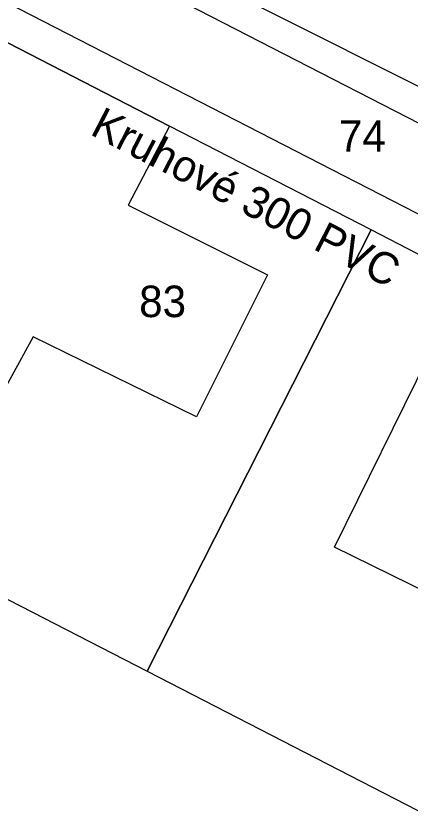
# Model space of a CAD drawing. Extents: x -559654 to -559448, y -1076607 to -1076478.
# Drawn here: x -559576.11 to -559557.35, y -1076565.25 to -1076527.73 of the extents above; entities that cross this region are included whole.
import ezdxf

# ---------------------------------------------------------------- set-up
doc = ezdxf.new("R2010")
doc.units = 0
for name, color, linetype in [('Kanalizační stoka', 7, 'Continuous'), ('Parcela-polygon', 7, 'Continuous'), ('Parcela-text', 7, 'Continuous'), ('Popis kmenové stoky', 7, 'Continuous'), ('Vodovodní řad', 7, 'Continuous')]:
    doc.layers.add(name, color=color, linetype=linetype)

msp = doc.modelspace()

# ---------------------------------------------------------------- linework, layer by layer
at = {"layer": 'Kanalizační stoka'}
msp.add_lwpolyline([(-559542.148, -1076544.787), (-559590.298, -1076520.017)], dxfattribs=at)
at = {"layer": 'Parcela-polygon'}
for p, q in [((-559587.727, -1076549.716), (-559569.856, -1076558.926)), ((-559569.856, -1076558.926), (-559551.999, -1076568.129))]:
    msp.add_line(p, q, dxfattribs=at)
for points in [[(-559598.18, -1076518.16), (-559629.27, -1076502.23), (-559633.72, -1076500.39), (-559623.33, -1076497.36), (-559616.19, -1076501.28), (-559573.81, -1076522.62), (-559555.89, -1076531.62), (-559538.18, -1076540.8), (-559520.56, -1076549.81), (-559502.55, -1076559.13), (-559485.32, -1076568.19), (-559489.07, -1076574.14), (-559505.11, -1076565.7), (-559518.69, -1076558.79), (-559538.34, -1076548.73), (-559546.54, -1076544.48), (-559559.21, -1076537.91), (-559568.79, -1076532.99), (-559577, -1076528.76), (-559595.22, -1076519.64)], [(-559568.79, -1076532.99), (-559570.76, -1076536.75), (-559564.14, -1076540.06), (-559567.52, -1076546.81), (-559575.28, -1076543.01), (-559577.42, -1076546.89), (-559581.41, -1076544.47), (-559584.1, -1076543.03), (-559584.34, -1076542.9), (-559579.53, -1076533.07), (-559577, -1076528.76)], [(-559556.49, -1076543.97), (-559548.32, -1076548.02), (-559546.54, -1076544.48), (-559538.34, -1076548.73), (-559542.4, -1076556.72), (-559545.15, -1076562.4), (-559547.78, -1076561.13), (-559550.05, -1076564.71), (-559551.63, -1076563.88), (-559549.91, -1076560.67), (-559552.84, -1076557), (-559560.94, -1076553.02)]]:
    msp.add_lwpolyline(points, close=True, dxfattribs=at)
for points in [[(-559548.356, -1076508.596), (-559549.45, -1076510.66), (-559551.72, -1076509.51), (-559557.46, -1076506.54), (-559559.19, -1076509.84), (-559565.46, -1076506.3), (-559573.81, -1076522.62), (-559555.89, -1076531.62), (-559545.04, -1076510.049)], [(-559569.856, -1076558.926), (-559559.21, -1076537.91), (-559568.79, -1076532.99), (-559570.76, -1076536.75), (-559564.14, -1076540.06), (-559567.52, -1076546.81), (-559575.28, -1076543.01), (-559577.42, -1076546.89), (-559581.41, -1076544.47), (-559584.1, -1076543.03), (-559584.34, -1076542.9), (-559587.727, -1076549.716)], [(-559551.999, -1076568.129), (-559551.22, -1076566.57), (-559550.05, -1076564.71), (-559551.63, -1076563.88), (-559549.91, -1076560.67), (-559552.84, -1076557), (-559560.94, -1076553.02), (-559556.49, -1076543.97), (-559548.32, -1076548.02), (-559546.54, -1076544.48), (-559559.21, -1076537.91), (-559569.856, -1076558.926)]]:
    msp.add_lwpolyline(points, dxfattribs=at)
at = {"layer": 'Vodovodní řad'}
msp.add_lwpolyline([(-559593.267, -1076491.395), (-559624.029, -1076495.839), (-559624.9, -1076495.951), (-559625.488, -1076496.027), (-559625.404, -1076497.654), (-559619.475, -1076500.701), (-559618.245, -1076501.333), (-559615.438, -1076502.776), (-559591.192, -1076515.237), (-559582.087, -1076519.916), (-559544.618, -1076539.173), (-559534.23, -1076544.512), (-559532.371, -1076545.439), (-559530.757, -1076546.244), (-559525.83, -1076548.702), (-559513.543, -1076555.186), (-559509.507, -1076557.365), (-559508.97, -1076557.619), (-559494.604, -1076565.581), (-559494.539, -1076565.616), (-559485.627, -1076570.145)], dxfattribs=at)

# ---------------------------------------------------------------- texts
at = {"layer": 'Parcela-text'}
for s, p in [('74', (-559560.74, -1076534.2)), ('83', (-559570.24, -1076542.07))]:
    msp.add_text(s, height=1.5, dxfattribs=at).set_placement(p)
at = {"layer": 'Popis kmenové stoky'}
msp.add_text('Kruhové 300 PVC', height=1.5, rotation=332.7772, dxfattribs=at).set_placement((-559572.629, -1076533.354))

doc.saveas('drawing.dxf')
